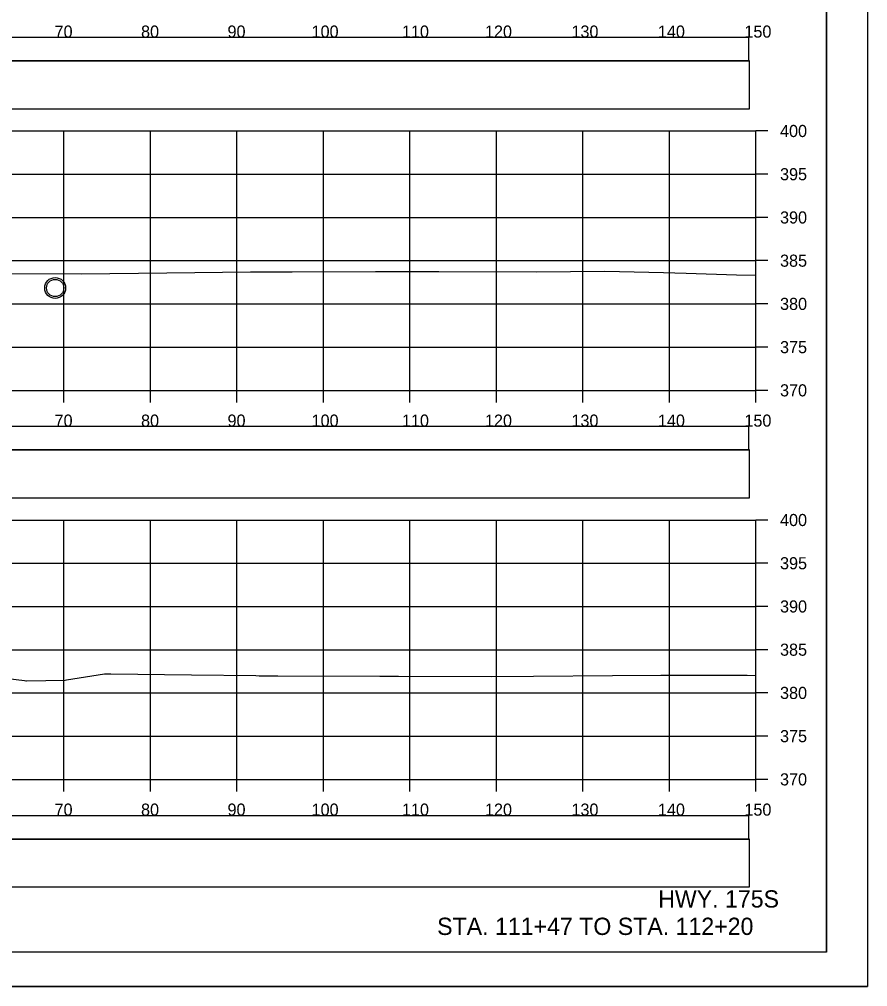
# Model space of a CAD drawing. Extents: x -37291014 to -37290680, y -936053 to -933067.
# Drawn here: x -37290778.3 to -37290680.2, y -933706.6 to -933594.7 of the extents above; entities that cross this region are included whole.
import ezdxf

# ---------------------------------------------------------------- set-up
doc = ezdxf.new("R2010")
doc.units = 0
for name, color, linetype in [('Default', 7, 'Continuous'), ('R_Axis', 7, 'Continuous'), ('R_Axis Annot', 7, 'Continuous'), ('R_Border', 7, 'Continuous'), ('R_Draft', 7, 'Continuous'), ('R_Exist Surface', 7, 'Continuous'), ('R_Grid', 7, 'Continuous'), ('R_No Plot', 7, 'Continuous'), ('R_Water', 7, 'Continuous')]:
    doc.layers.add(name, color=color, linetype=linetype)

msp = doc.modelspace()

# ---------------------------------------------------------------- linework, layer by layer
at = {"layer": 'Default'}
for points in [[(-37290992.31, -933599.51), (-37290693.89, -933599.51), (-37290693.89, -933596.81), (-37290992.31, -933596.81)], [(-37290992.26, -933605.03), (-37290693.84, -933605.03), (-37290693.84, -933599.51), (-37290992.26, -933599.51)], [(-37290992.31, -933644.51), (-37290693.89, -933644.51), (-37290693.89, -933641.81), (-37290992.31, -933641.81)], [(-37290992.26, -933650.03), (-37290693.84, -933650.03), (-37290693.84, -933644.51), (-37290992.26, -933644.51)], [(-37290992.31, -933689.51), (-37290693.89, -933689.51), (-37290693.89, -933686.81), (-37290992.31, -933686.81)], [(-37290992.26, -933695.03), (-37290693.84, -933695.03), (-37290693.84, -933689.51), (-37290992.26, -933689.51)]]:
    msp.add_lwpolyline(points, close=True, dxfattribs=at)
at = {"layer": 'R_Axis'}
for p, q in [((-37290693.1, -933637.61), (-37290693.1, -933607.61)), ((-37290691.7, -933607.61), (-37290693.1, -933607.61)), ((-37290691.7, -933612.61), (-37290693.1, -933612.61)), ((-37290691.7, -933617.61), (-37290693.1, -933617.61)), ((-37290691.7, -933622.61), (-37290693.1, -933622.61)), ((-37290691.7, -933627.61), (-37290693.1, -933627.61)), ((-37290691.7, -933632.61), (-37290693.1, -933632.61)), ((-37290993.1, -933637.61), (-37290693.1, -933637.61)), ((-37290773.1, -933639.01), (-37290773.1, -933637.61)), ((-37290763.1, -933639.01), (-37290763.1, -933637.61)), ((-37290753.1, -933639.01), (-37290753.1, -933637.61)), ((-37290743.1, -933639.01), (-37290743.1, -933637.61)), ((-37290733.1, -933639.01), (-37290733.1, -933637.61)), ((-37290723.1, -933639.01), (-37290723.1, -933637.61)), ((-37290713.1, -933639.01), (-37290713.1, -933637.61)), ((-37290703.1, -933639.01), (-37290703.1, -933637.61)), ((-37290693.1, -933639.01), (-37290693.1, -933637.61)), ((-37290691.7, -933637.61), (-37290693.1, -933637.61)), ((-37290693.1, -933682.61), (-37290693.1, -933652.61)), ((-37290691.7, -933652.61), (-37290693.1, -933652.61)), ((-37290691.7, -933657.61), (-37290693.1, -933657.61)), ((-37290691.7, -933662.61), (-37290693.1, -933662.61)), ((-37290691.7, -933667.61), (-37290693.1, -933667.61)), ((-37290691.7, -933672.61), (-37290693.1, -933672.61)), ((-37290691.7, -933677.61), (-37290693.1, -933677.61)), ((-37290993.1, -933682.61), (-37290693.1, -933682.61)), ((-37290773.1, -933684.01), (-37290773.1, -933682.61)), ((-37290763.1, -933684.01), (-37290763.1, -933682.61)), ((-37290753.1, -933684.01), (-37290753.1, -933682.61)), ((-37290743.1, -933684.01), (-37290743.1, -933682.61)), ((-37290733.1, -933684.01), (-37290733.1, -933682.61)), ((-37290723.1, -933684.01), (-37290723.1, -933682.61)), ((-37290713.1, -933684.01), (-37290713.1, -933682.61)), ((-37290703.1, -933684.01), (-37290703.1, -933682.61)), ((-37290693.1, -933684.01), (-37290693.1, -933682.61)), ((-37290691.7, -933682.61), (-37290693.1, -933682.61))]:
    msp.add_line(p, q, dxfattribs=at)
at = {"layer": 'R_Border'}
for q in [(-37290684.92, -933497.15), (-37291001.1, -933702.61)]:
    msp.add_line((-37290684.92, -933702.61), q, dxfattribs=at)
at = {"layer": 'R_Exist Surface'}
for points in [[(-37290782.58, -933624.09), (-37290771.08, -933624.15), (-37290761.19, -933624.03), (-37290751.52, -933623.92), (-37290746.73, -933623.89), (-37290737.07, -933623.87), (-37290732.57, -933623.88), (-37290729.75, -933623.87), (-37290718.5, -933623.89), (-37290710.56, -933623.84), (-37290703.79, -933623.98), (-37290701.15, -933624.06), (-37290695.33, -933624.24), (-37290693.1, -933624.3)], [(-37290782.48, -933670.59), (-37290777.67, -933671.19), (-37290777.51, -933671.2), (-37290777.43, -933671.2), (-37290772.98, -933671.13), (-37290772.8, -933671.11), (-37290768.43, -933670.39), (-37290767.7, -933670.41), (-37290758.36, -933670.52), (-37290750.92, -933670.61), (-37290750.53, -933670.62), (-37290748.37, -933670.64), (-37290736.59, -933670.69), (-37290734.4, -933670.68), (-37290723.63, -933670.71), (-37290718.8, -933670.67), (-37290709.66, -933670.58), (-37290704.09, -933670.57), (-37290694.1, -933670.56), (-37290693.1, -933670.6)]]:
    msp.add_lwpolyline(points, dxfattribs=at)
at = {"layer": 'R_Grid'}
for p, q in [((-37290993.1, -933607.61), (-37290693.1, -933607.61)), ((-37290773.1, -933637.61), (-37290773.1, -933607.61)), ((-37290763.1, -933637.61), (-37290763.1, -933607.61)), ((-37290753.1, -933637.61), (-37290753.1, -933607.61)), ((-37290743.1, -933637.61), (-37290743.1, -933607.61)), ((-37290733.1, -933637.61), (-37290733.1, -933607.61)), ((-37290723.1, -933637.61), (-37290723.1, -933607.61)), ((-37290713.1, -933637.61), (-37290713.1, -933607.61)), ((-37290703.1, -933637.61), (-37290703.1, -933607.61)), ((-37290693.1, -933637.61), (-37290693.1, -933607.61)), ((-37290993.1, -933612.61), (-37290693.1, -933612.61)), ((-37290993.1, -933617.61), (-37290693.1, -933617.61)), ((-37290993.1, -933622.61), (-37290693.1, -933622.61)), ((-37290993.1, -933627.61), (-37290693.1, -933627.61)), ((-37290993.1, -933632.61), (-37290693.1, -933632.61)), ((-37290993.1, -933637.61), (-37290693.1, -933637.61)), ((-37290993.1, -933652.61), (-37290693.1, -933652.61)), ((-37290773.1, -933682.61), (-37290773.1, -933652.61)), ((-37290763.1, -933682.61), (-37290763.1, -933652.61)), ((-37290753.1, -933682.61), (-37290753.1, -933652.61)), ((-37290743.1, -933682.61), (-37290743.1, -933652.61)), ((-37290733.1, -933682.61), (-37290733.1, -933652.61)), ((-37290723.1, -933682.61), (-37290723.1, -933652.61)), ((-37290713.1, -933682.61), (-37290713.1, -933652.61)), ((-37290703.1, -933682.61), (-37290703.1, -933652.61)), ((-37290693.1, -933682.61), (-37290693.1, -933652.61)), ((-37290993.1, -933657.61), (-37290693.1, -933657.61)), ((-37290993.1, -933662.61), (-37290693.1, -933662.61)), ((-37290993.1, -933667.61), (-37290693.1, -933667.61)), ((-37290993.1, -933672.61), (-37290693.1, -933672.61)), ((-37290993.1, -933677.61), (-37290693.1, -933677.61)), ((-37290993.1, -933682.61), (-37290693.1, -933682.61))]:
    msp.add_line(p, q, dxfattribs=at)
at = {"layer": 'R_No Plot'}
msp.add_line((-37291013.5, -933706.58), (-37290680.17, -933706.58), dxfattribs=at)
for points in [[(-37291013.51, -933493.25), (-37290680.17, -933493.25), (-37290680.17, -933706.59), (-37291013.51, -933706.59)], [(-37290767.18, -933497.15), (-37290747.56, -933497.15), (-37290747.56, -933507.03), (-37290731.45, -933507.03), (-37290708.25, -933507.03), (-37290708.25, -933531.36), (-37290684.92, -933531.36), (-37290684.92, -933702.61), (-37291001.1, -933702.61), (-37291001.1, -933497.15)]]:
    msp.add_lwpolyline(points, close=True, dxfattribs=at)
msp.add_circle((-37290774.12, -933625.77), 1.21, dxfattribs=at)
at = {"layer": 'R_Water'}
msp.add_circle((-37290774.12, -933625.77), 1, dxfattribs=at)

# ---------------------------------------------------------------- texts
at = {"layer": 'R_Axis Annot'}
for s, p in [('70', (-37290774.19, -933596.81)), ('80', (-37290764.19, -933596.81)), ('90', (-37290754.19, -933596.81)), ('100', (-37290744.47, -933596.81)), ('110', (-37290734.02, -933596.81)), ('120', (-37290724.42, -933596.81)), ('130', (-37290714.42, -933596.81)), ('140', (-37290704.42, -933596.81)), ('150', (-37290694.42, -933596.81)), ('400', (-37290690.3, -933608.31)), ('395', (-37290690.3, -933613.31)), ('390', (-37290690.3, -933618.31)), ('385', (-37290690.3, -933623.31)), ('380', (-37290690.3, -933628.31)), ('375', (-37290690.3, -933633.31)), ('370', (-37290690.3, -933638.31)), ('70', (-37290774.19, -933641.81)), ('80', (-37290764.19, -933641.81)), ('90', (-37290754.19, -933641.81)), ('100', (-37290744.47, -933641.81)), ('110', (-37290734.02, -933641.81)), ('120', (-37290724.42, -933641.81)), ('130', (-37290714.42, -933641.81)), ('140', (-37290704.42, -933641.81)), ('150', (-37290694.42, -933641.81)), ('400', (-37290690.3, -933653.31)), ('395', (-37290690.3, -933658.31)), ('390', (-37290690.3, -933663.31)), ('385', (-37290690.3, -933668.31)), ('380', (-37290690.3, -933673.31)), ('375', (-37290690.3, -933678.31)), ('370', (-37290690.3, -933683.31)), ('70', (-37290774.19, -933686.81)), ('80', (-37290764.19, -933686.81)), ('90', (-37290754.19, -933686.81)), ('100', (-37290744.47, -933686.81)), ('110', (-37290734.02, -933686.81)), ('120', (-37290724.42, -933686.81)), ('130', (-37290714.42, -933686.81)), ('140', (-37290704.42, -933686.81)), ('150', (-37290694.42, -933686.81))]:
    msp.add_text(s, height=1.4, dxfattribs=at).set_placement(p)
at = {"layer": 'R_Draft'}
for s, p in [('HWY. 175S', (-37290704.39, -933697.44)), ('STA. 111+47 TO STA. 112+20', (-37290729.95, -933700.61))]:
    msp.add_text(s, height=2, dxfattribs=at).set_placement(p)

doc.saveas('drawing.dxf')
